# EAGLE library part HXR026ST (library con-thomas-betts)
THOMAS&BETTS
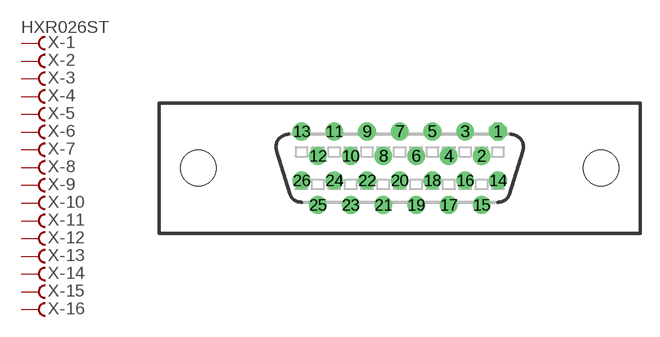
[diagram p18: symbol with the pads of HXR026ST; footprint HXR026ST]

Designator prefix X; gates -1=FV -2=F -3=F -4=F -5=F -6=F -7=F -8=F -9=F -10=F -11=F -12=F -13=F -14=F -15=F -16=F -17=F -18=F -19=F -20=F -21=F -22=F -23=F -24=F -25=F -26=F

## HXR026ST (OC_FARNELL: unknown; OC_NEWARK: unknown)  [HXR026ST]
1  -1:F  pas
2  -2:F  pas
3  -3:F  pas
4  -4:F  pas
5  -5:F  pas
6  -6:F  pas
7  -7:F  pas
8  -8:F  pas
9  -9:F  pas
10  -10:F  pas
11  -11:F  pas
12  -12:F  pas
13  -13:F  pas
14  -14:F  pas
15  -15:F  pas
16  -16:F  pas
17  -17:F  pas
18  -18:F  pas
19  -19:F  pas
20  -20:F  pas
21  -21:F  pas
22  -22:F  pas
23  -23:F  pas
24  -24:F  pas
25  -25:F  pas
26  -26:F  pas

## Footprint HXR026ST (pad centres in mm)
THOMAS&BETTS HFR026ST29xx, HHR026ST29xx
drill 0.864 octagon: 1 7.62,2.857
drill 0.864 round: 2 6.35,0.953; 3 5.08,2.857; 4 3.81,0.953; 5 2.54,2.857; 6 1.27,0.953; 7 0,2.857; 8 -1.27,0.953; 9 -2.54,2.857; 10 -3.81,0.953; 11 -5.08,2.857; 12 -6.35,0.953; 13 -7.62,2.857; 14 7.62,-0.953; 15 6.35,-2.857; 16 5.08,-0.953; 17 3.81,-2.857; 18 2.54,-0.953; 19 1.27,-2.857; 20 0,-0.953; 21 -1.27,-2.857; 22 -2.54,-0.953; 23 -3.81,-2.857; 24 -5.08,-0.953; 25 -6.35,-2.857; 26 -7.62,-0.953
hole 2.769 at 15.621,0.013
hole 2.769 at -15.621,0.013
